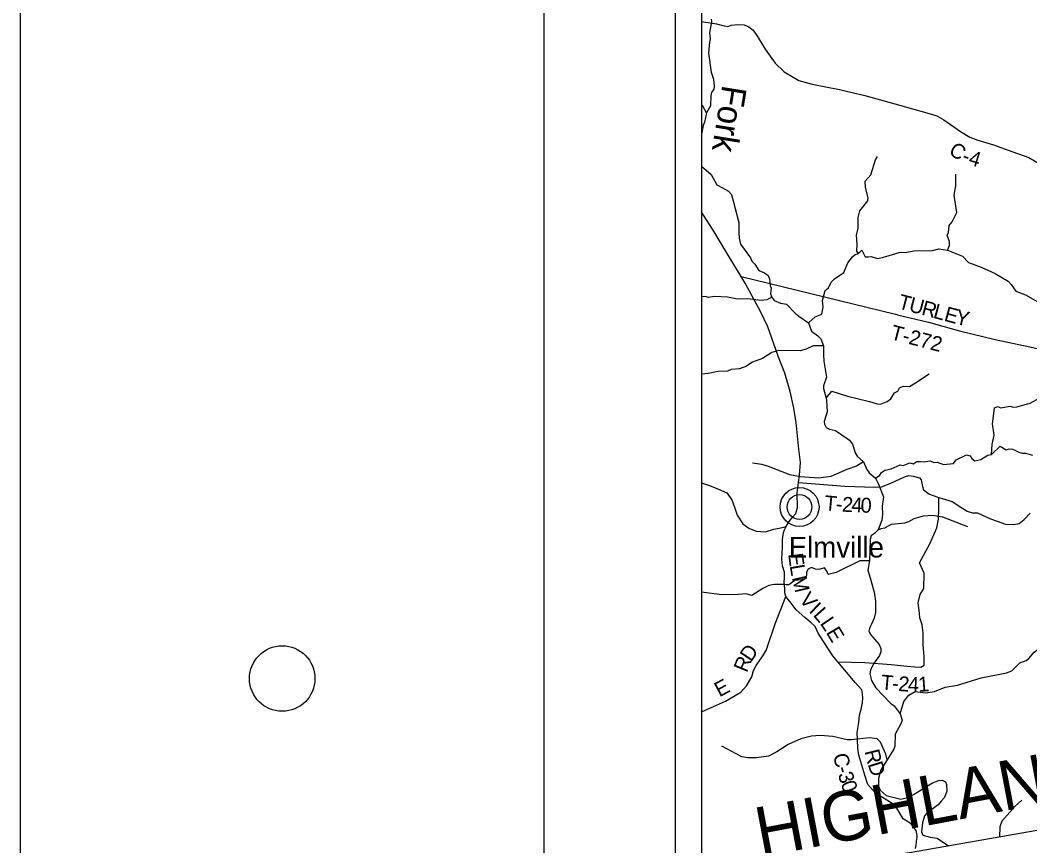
# Model space of a CAD drawing. Extents: x 0 to 34, y 0 to 22.
# Drawn here: x 0 to 3.854, y 14.612 to 17.761 of the extents above; entities that cross this region are included whole.
import ezdxf

# ---------------------------------------------------------------- set-up
doc = ezdxf.new("R2010")
doc.units = 0
for name, color, linetype in [('GM_X_Adjacent_County', 7, 'Continuous'), ('GM_X_Adjacent_County_Text', 7, 'Continuous'), ('GM_X_County', 7, 'Continuous'), ('GM_X_County_Road', 7, 'Continuous'), ('GM_X_County_Road_Text', 7, 'Continuous'), ('GM_X_Minor_River', 7, 'Continuous'), ('GM_X_Minor_River_Text', 7, 'Continuous'), ('GM_X_Township_Road', 7, 'Continuous'), ('GM_X_Township_Road_Text', 7, 'Continuous'), ('GM_X_Township_ROW', 7, 'Continuous'), ('GM_X_Unincorporated', 7, 'Continuous'), ('GM_X_Unincorporated_Location', 7, 'Continuous'), ('GM_X_Unincorporated_Text', 7, 'Continuous'), ('SH_Border', 7, 'Continuous'), ('SH_Cut_Line', 7, 'Continuous'), ('SH_Data', 7, 'Continuous')]:
    doc.layers.add(name, color=color, linetype=linetype)

msp = doc.modelspace()

# ---------------------------------------------------------------- linework, layer by layer
at = {"layer": 'GM_X_Adjacent_County'}
msp.add_lwpolyline([(9.4, 14.9965), (8.815, 15.0315), (8.2967, 15.0626), (8.1206, 15.0731), (7.1103, 15.1434), (6.9032, 15.1545), (6.5214, 15.204), (6.1992, 15.1249), (5.0219, 14.8699), (4.9843, 14.8636), (3.402, 14.5859), (3.2736, 14.5654), (2.6, 14.46)], dxfattribs=at)
at = {"layer": 'GM_X_County'}
msp.add_lwpolyline([(7.6111, 20.9006), (2.6, 20.9006), (2.6, 14.46)], dxfattribs=at)
at = {"layer": 'GM_X_County_Road'}
for points in [[(2.6, 17.757), (2.6572, 17.7478), (2.6864, 17.7403), (2.7016, 17.7378), (2.7156, 17.742), (2.7376, 17.7456), (2.7638, 17.7435), (2.7809, 17.736), (2.798, 17.724), (2.8149, 17.6998), (2.8432, 17.6514), (2.8819, 17.5973), (2.9155, 17.5645), (2.9722, 17.5311), (3.0227, 17.5173), (3.1271, 17.4975), (3.2243, 17.4742), (3.3387, 17.4422), (3.4154, 17.4207), (3.4519, 17.4103), (3.4994, 17.3969), (3.5256, 17.3819), (3.5896, 17.3364), (3.6247, 17.3153), (3.6547, 17.3034), (3.7155, 17.2859), (3.7888, 17.2594), (3.8496, 17.2378), (3.8934, 17.2122)], [(3.4175, 14.6019), (3.4198, 14.6133), (3.4216, 14.6286), (3.4225, 14.6372), (3.4231, 14.6451), (3.4232, 14.6521), (3.4229, 14.6572), (3.4215, 14.664), (3.4195, 14.6697), (3.415, 14.6769), (3.4011, 14.6957), (3.3707, 14.7144), (3.3562, 14.7394), (3.3435, 14.759), (3.3279, 14.7733), (3.2776, 14.8049), (3.2559, 14.8234), (3.2356, 14.8453), (3.224, 14.8809), (3.2015, 14.957), (3.1976, 14.9851), (3.1949, 15.0439), (3.2007, 15.0819), (3.2036, 15.11), (3.2095, 15.1328), (3.2147, 15.1567), (3.2168, 15.1757), (3.2156, 15.1917), (3.2128, 15.2068), (3.1872, 15.2351), (3.1205, 15.3137), (3.1013, 15.3363), (3.0656, 15.3908), (3.0461, 15.4225), (3.0345, 15.449), (3.0178, 15.4633), (2.9949, 15.4829), (2.9621, 15.5116), (2.9433, 15.538), (2.9219, 15.5633), (2.9192, 15.5766), (2.9183, 15.5898), (2.9159, 15.6213), (2.9173, 15.632), (2.9172, 15.6555), (2.9094, 15.6797), (2.9077, 15.7048), (2.9097, 15.7511), (2.9103, 15.7803), (2.9139, 15.8069), (2.9173, 15.8175), (2.9236, 15.8297), (2.9352, 15.8491), (2.9492, 15.8671), (2.9612, 15.88), (2.9668, 15.9028), (2.9656, 15.9567), (2.9713, 15.9982), (2.9751, 16.0258), (2.9782, 16.0744), (2.9714, 16.1252), (2.962, 16.2265), (2.9529, 16.2811), (2.9389, 16.3444), (2.9183, 16.4152), (2.8936, 16.48), (2.8535, 16.5921), (2.8262, 16.6507), (2.7674, 16.7585), (2.752, 16.784), (2.7027, 16.8655), (2.6456, 16.9601), (2.6077, 17.0172), (2.6, 17.0296)], [(2.6, 15.9971), (2.6306, 15.9865), (2.666, 15.9723), (2.6968, 15.9585), (2.7167, 15.932), (2.7279, 15.8999), (2.7371, 15.8737), (2.7586, 15.8401), (2.7807, 15.8235), (2.8092, 15.8116), (2.8445, 15.8095), (2.877, 15.8203), (2.8971, 15.8242), (2.9236, 15.8297)]]:
    msp.add_lwpolyline(points, dxfattribs=at)
at = {"layer": 'GM_X_Minor_River'}
for points in [[(2.6379, 17.7657), (2.6386, 17.7547), (2.6306, 17.7135), (2.6338, 17.6907), (2.631, 17.6778), (2.6268, 17.6351), (2.6378, 17.5626), (2.6458, 17.5367), (2.649, 17.5101), (2.647, 17.498), (2.6393, 17.4852), (2.6358, 17.4727), (2.6346, 17.4348), (2.62, 17.4077), (2.6124, 17.3721), (2.6063, 17.3601), (2.6, 17.3267)], [(2.62, 17.4077), (2.6062, 17.434), (2.6, 17.4372)], [(3.1996, 16.8718), (3.1932, 16.8802), (3.195, 16.9074), (3.1923, 16.9412), (3.1979, 16.968), (3.1987, 17.009), (3.2053, 17.0339), (3.2352, 17.0719), (3.2369, 17.0844), (3.227, 17.1228), (3.2254, 17.1474), (3.2464, 17.1715), (3.2644, 17.2282), (3.2717, 17.2414)], [(2.6, 17.204), (2.6373, 17.1729), (2.6596, 17.134), (2.6807, 17.1217), (2.7037, 17.1093), (2.7149, 17.0971), (2.7433, 16.9903), (2.7426, 16.9513), (2.7439, 16.9293), (2.7493, 16.9073), (2.7878, 16.8553), (2.7926, 16.8416), (2.8042, 16.8302), (2.8195, 16.8061), (2.8409, 16.798), (2.8545, 16.7872), (2.8596, 16.775), (2.862, 16.7492), (2.8668, 16.7393), (2.864, 16.7185), (2.8673, 16.7067), (2.8774, 16.6926), (2.9015, 16.6825), (2.9253, 16.6781), (2.9597, 16.6422), (2.9717, 16.6318), (3.0093, 16.6072), (3.0203, 16.5745), (3.0448, 16.5572), (3.0564, 16.5457), (3.0667, 16.5198), (3.0667, 16.4857), (3.0676, 16.4611), (3.0776, 16.4), (3.0663, 16.3667), (3.0658, 16.3561), (3.0768, 16.32), (3.0771, 16.3102), (3.0805, 16.2673), (3.0684, 16.2299), (3.0694, 16.22), (3.0769, 16.2071), (3.0897, 16.2013), (3.1123, 16.1965), (3.1563, 16.1654), (3.166, 16.1588), (3.1765, 16.1443), (3.1868, 16.1105), (3.1942, 16.0983), (3.2186, 16.0761), (3.2319, 16.0479), (3.2409, 16.0353), (3.2649, 16.0142), (3.276, 15.9918), (3.2952, 15.9435), (3.2899, 15.9075), (3.2919, 15.8768), (3.2894, 15.8541), (3.2747, 15.8171), (3.2617, 15.8051), (3.2483, 15.7939)], [(3.5398, 16.8847), (3.5468, 16.9025), (3.547, 16.9169), (3.5381, 16.9397), (3.5435, 16.9518), (3.5453, 16.9779), (3.5568, 16.9922), (3.5753, 17.0273), (3.5703, 17.0607), (3.5654, 17.0941), (3.5714, 17.13), (3.5715, 17.1747)], [(3.0093, 16.6072), (3.0349, 16.6293), (3.06, 16.64), (3.0644, 16.6673), (3.0627, 16.6916), (3.0722, 16.7297), (3.0852, 16.7402), (3.0956, 16.7625), (3.1082, 16.7753), (3.1436, 16.7992), (3.1595, 16.8361), (3.1775, 16.8583), (3.1874, 16.867), (3.1996, 16.8718), (3.2129, 16.8838), (3.2252, 16.8582), (3.2377, 16.8589), (3.2475, 16.8595), (3.272, 16.8525), (3.2917, 16.8557), (3.3547, 16.8748), (3.3642, 16.8766), (3.3782, 16.8746), (3.4112, 16.8814), (3.4819, 16.8823), (3.5062, 16.8892), (3.5398, 16.8847), (3.5839, 16.8665), (3.5967, 16.8614), (3.6199, 16.8366), (3.6686, 16.8194), (3.7217, 16.7954), (3.7713, 16.7657), (3.7826, 16.7527), (3.8008, 16.7279), (3.837, 16.7139), (3.8841, 16.6869)], [(2.8673, 16.7067), (2.8631, 16.7011), (2.8498, 16.6944), (2.8285, 16.692), (2.7779, 16.6989), (2.7378, 16.6974), (2.6993, 16.7042), (2.6501, 16.7077), (2.6277, 16.703), (2.6164, 16.7077), (2.6, 16.7055)], [(3.0667, 16.5198), (3.0266, 16.5191), (3, 16.5069), (2.9768, 16.5006), (2.8963, 16.501), (2.8693, 16.4934), (2.8339, 16.4706), (2.7952, 16.4566), (2.77, 16.4398), (2.745, 16.4309), (2.7132, 16.4286), (2.7003, 16.4219), (2.6647, 16.4215), (2.6264, 16.4131), (2.6, 16.4117)], [(3.0768, 16.32), (3.0979, 16.346), (3.1583, 16.3268), (3.2421, 16.3074), (3.2711, 16.298), (3.2839, 16.2964), (3.309, 16.3064), (3.3227, 16.3176), (3.3373, 16.3398), (3.3499, 16.3465), (3.3564, 16.3586), (3.3697, 16.3653), (3.3943, 16.3639), (3.4179, 16.3781), (3.4697, 16.412)], [(3.7073, 16.1046), (3.7103, 16.1425), (3.7179, 16.178), (3.7111, 16.2213), (3.7173, 16.2709), (3.7193, 16.283), (3.7307, 16.2874), (3.7427, 16.2828), (3.778, 16.2896), (3.7908, 16.2853), (3.8037, 16.286), (3.8549, 16.3002), (3.88, 16.314), (3.8917, 16.3128), (3.9168, 16.3243), (3.9429, 16.3244), (3.9649, 16.3329)], [(3.2649, 16.0142), (3.2813, 16.0255), (3.2882, 16.0356), (3.3004, 16.045), (3.3246, 16.0497), (3.3585, 16.0652), (3.3705, 16.0632), (3.3956, 16.0725), (3.4084, 16.0693), (3.4218, 16.0779), (3.4361, 16.0781), (3.4475, 16.0761), (3.4733, 16.0808), (3.4868, 16.0746), (3.4997, 16.0748), (3.5246, 16.0659), (3.5621, 16.0708), (3.5732, 16.0844), (3.6123, 16.1037), (3.6259, 16.0994), (3.6319, 16.0895), (3.6439, 16.081), (3.6666, 16.0857), (3.694, 16.1025), (3.7073, 16.1046), (3.7409, 16.1361), (3.7631, 16.1223), (3.7745, 16.126), (3.7877, 16.1254), (3.7994, 16.1196), (3.8118, 16.1131), (3.825, 16.1092), (3.8375, 16.1102), (3.8639, 16.1016)], [(3.2186, 16.0761), (3.1923, 16.0604), (3.1547, 16.0472), (3.0939, 16.0201), (3.0481, 16.0141), (2.977, 16.019), (2.9377, 16.0273), (2.8567, 16.0588), (2.8303, 16.0666), (2.7955, 16.0719)], [(3.2747, 15.8171), (3.2861, 15.8227), (3.3001, 15.8244), (3.326, 15.8389), (3.3767, 15.8445), (3.3919, 15.8493), (3.4121, 15.8608), (3.4481, 15.8707), (3.4818, 15.873), (3.5207, 15.8662), (3.6164, 15.8296)], [(3.2483, 15.7939), (3.244, 15.7803), (3.2417, 15.6992), (3.2357, 15.6632), (3.2437, 15.6347), (3.2595, 15.5793), (3.2652, 15.5455), (3.2644, 15.5015), (3.2596, 15.4807), (3.2496, 15.4569), (3.2434, 15.4445), (3.2398, 15.432), (3.2454, 15.4183), (3.2791, 15.3801), (3.285, 15.3649), (3.2848, 15.3524), (3.2794, 15.3384), (3.2571, 15.3057), (3.2459, 15.2823), (3.2435, 15.2683), (3.2489, 15.2425), (3.2665, 15.2146), (3.3223, 15.1561), (3.3365, 15.1461), (3.3589, 15.1148), (3.3659, 15.0908), (3.3616, 15.0776), (3.3396, 15.0377), (3.3388, 14.9918), (3.3341, 14.9801), (3.309, 14.9394)], [(3.2417, 15.6992), (3.2046, 15.6984), (3.1142, 15.655), (3.0846, 15.6469), (3.0783, 15.6591), (3.0704, 15.6721), (3.0488, 15.6655), (3.0352, 15.6667), (3.0201, 15.6729), (3.008, 15.6674), (3.001, 15.6553), (3.0009, 15.6424), (2.9947, 15.63), (2.9818, 15.626), (2.9568, 15.6239), (2.934, 15.6075), (2.9234, 15.6068), (2.9132, 15.6081), (2.8795, 15.6084), (2.8571, 15.6044), (2.834, 15.5937), (2.7925, 15.5664), (2.7698, 15.5727), (2.7414, 15.5703), (2.6775, 15.5695), (2.6, 15.5795)], [(3.3589, 15.1148), (3.3734, 15.162), (3.3918, 15.1869), (3.4161, 15.201), (3.4558, 15.1949), (3.4899, 15.1999), (3.5306, 15.2166), (3.5772, 15.2241), (3.6683, 15.2523), (3.7649, 15.2711), (3.7851, 15.2796), (3.8152, 15.3096), (3.8395, 15.3181), (3.8495, 15.326), (3.8698, 15.3508), (3.9109, 15.3808)], [(3.309, 14.9394), (3.3044, 14.9618), (3.2841, 15.0075), (3.2713, 15.0202), (3.2419, 15.0231), (3.1714, 15.0158), (3.1559, 15.0164), (3.1012, 15.0283), (3.0535, 15.0325), (3.0198, 15.0298), (2.98, 15.0196), (2.931, 14.9977), (2.8883, 14.9697), (2.8568, 14.9538), (2.8106, 14.9478), (2.7985, 14.9475), (2.7758, 14.9474), (2.7542, 14.9514), (2.6786, 14.9919)], [(3.309, 14.9394), (3.2853, 14.901), (3.2763, 14.8689), (3.276, 14.8393), (3.2823, 14.8237), (3.3048, 14.8038), (3.3618, 14.7903), (3.3872, 14.7962), (3.41, 14.8073), (3.4827, 14.8517), (3.5059, 14.8606), (3.5187, 14.8619), (3.5315, 14.8558), (3.5356, 14.8462), (3.5369, 14.8205), (3.5283, 14.7967), (3.5149, 14.7816), (3.5042, 14.7685), (3.46, 14.7367), (3.4523, 14.7258), (3.4445, 14.6997), (3.4407, 14.6649), (3.4459, 14.6519), (3.4727, 14.6448), (3.5003, 14.6404), (3.5432, 14.6119)], [(3.8233, 14.7855), (3.7976, 14.7631), (3.7471, 14.706), (3.7394, 14.6838), (3.7384, 14.6442)]]:
    msp.add_lwpolyline(points, dxfattribs=at)
at = {"layer": 'GM_X_Township_Road'}
for points in [[(3.3418, 16.6396), (3.3482, 16.638), (3.4669, 16.6089), (3.5849, 16.5759), (3.7215, 16.5433), (3.8532, 16.5156), (3.9924, 16.4841), (4.3578, 16.3948)], [(2.9713, 15.9982), (3.1482, 15.9844), (3.2226, 15.9814), (3.2636, 15.9798), (3.2874, 15.9807), (3.323, 15.995), (3.3589, 16.0119), (3.3793, 16.0207), (3.3918, 16.0246), (3.4089, 16.0224), (3.4321, 16.0161), (3.4386, 16.0074), (3.4444, 15.982), (3.4475, 15.9699), (3.4712, 15.9534), (3.5031, 15.9422), (3.5068, 15.941), (3.5574, 15.9251), (3.5905, 15.904), (3.6145, 15.8886), (3.6351, 15.8819), (3.6544, 15.8824), (3.673, 15.873), (3.7031, 15.8588), (3.7285, 15.8498), (3.7605, 15.8394), (3.7927, 15.8377), (3.8135, 15.8409), (3.832, 15.8569), (3.855, 15.881)], [(2.6, 15.1233), (2.6923, 15.1631), (2.7505, 15.1985), (2.7726, 15.2219), (2.7932, 15.257), (2.799, 15.2802), (2.8093, 15.3002), (2.8326, 15.3327), (2.8475, 15.3569), (2.8817, 15.4581), (2.9219, 15.5633)], [(3.1205, 15.3137), (3.2236, 15.3114), (3.3244, 15.3041), (3.3858, 15.2977), (3.4149, 15.2949), (3.4373, 15.2936), (3.4499, 15.3011), (3.45, 15.3338), (3.4464, 15.3782), (3.447, 15.4241), (3.4426, 15.4549), (3.434, 15.4819), (3.4322, 15.4991)]]:
    msp.add_lwpolyline(points, dxfattribs=at)
at = {"layer": 'GM_X_Township_ROW'}
for points in [[(2.752, 16.784), (3.3414, 16.6397), (3.3418, 16.6396)], [(3.4322, 15.4991), (3.4321, 15.4995), (3.4279, 15.5385), (3.4348, 15.5707), (3.4486, 15.5934), (3.4508, 15.6522), (3.4331, 15.6914), (3.4718, 15.7641), (3.499, 15.8243), (3.5056, 15.858), (3.5058, 15.8956), (3.5068, 15.941)]]:
    msp.add_lwpolyline(points, dxfattribs=at)
at = {"layer": 'GM_X_Unincorporated'}
for radius in [0.0744, 0.0472]:
    msp.add_circle((2.9747, 15.9043), radius, dxfattribs=at)
at = {"layer": 'GM_X_Unincorporated_Location'}
msp.add_line((2.9747, 15.9043), (2.9747, 15.9043), dxfattribs=at)
at = {"layer": 'SH_Border'}
msp.add_lwpolyline([(2, 21.5), (33.5, 21.5), (33.5, 0.5), (2, 0.5)], close=True, dxfattribs=at)
msp.add_circle((1, 15.25), 0.125, dxfattribs=at)
at = {"layer": 'SH_Cut_Line'}
msp.add_lwpolyline([(0, 0), (34, 0), (34, 22), (0, 22)], close=True, dxfattribs=at)
at = {"layer": 'SH_Data'}
for p, q in [((2.5, 21), (2.5, 14)), ((2.6, 20.9), (2.6, 14.1))]:
    msp.add_line(p, q, dxfattribs=at)

# ---------------------------------------------------------------- texts
at = {"layer": 'GM_X_Adjacent_County_Text'}
msp.add_text('HIGHLAND COUNTY', height=0.189394, rotation=10.7426, dxfattribs=at).set_placement((2.8262, 14.568))
at = {"layer": 'GM_X_County_Road_Text'}
for s, rotation, p in [('C', 327.8353, (3.5404, 17.2526)), ('-', 338.7751, (3.5905, 17.2224)), ('4', 342.8142, (3.6163, 17.2125)), ('E', 277.3616, (2.9312, 15.7251)), ('L', 279.6904, (2.937, 15.6805)), ('M', 283.1153, (2.9449, 15.6351)), ('V', 309.3875, (2.9711, 15.5501)), ('I', 316.3635, (3.0079, 15.506)), ('L', 311.5189, (3.0239, 15.4909)), ('L', 304.1406, (3.0509, 15.4606)), ('E', 300.722, (3.0743, 15.4261)), ('C', 281.0551, (3.103, 14.9595)), ('R', 284.0665, (3.2224, 14.9723)), ('D', 287.2764, (3.2346, 14.9237)), ('3', 287.0163, (3.1205, 14.885)), ('-', 287.2584, (3.1136, 14.9072)), ('0', 288.5402, (3.1313, 14.85))]:
    msp.add_text(s, height=0.0568, rotation=rotation, dxfattribs=at).set_placement(p)
at = {"layer": 'GM_X_Minor_River_Text'}
msp.add_text('Fork', height=0.0947, rotation=260.8961, dxfattribs=at).set_placement((2.6803, 17.5171))
at = {"layer": 'GM_X_Township_Road_Text'}
for s, height, rotation, p in [('T', 0.0568, 345.0012, (3.3476, 16.6625)), ('U', 0.0568, 344.9954, (3.3887, 16.6515)), ('R', 0.0568, 344.9987, (3.437, 16.6385)), ('L', 0.0568, 345.0012, (3.482, 16.6265)), ('E', 0.0568, 345.0844, (3.5232, 16.6154)), ('Y', 0.0568, 346.5726, (3.5658, 16.6041)), ('T-272', 0.05682, 345.4273, (3.3187, 16.5452)), ('T', 0.0568, 354.7943, (3.0681, 15.8926)), ('2', 0.0568, 356.7853, (3.1359, 15.8868)), ('4', 0.0568, 357.7466, (3.1718, 15.8848)), ('0', 0.0568, 358.0486, (3.2071, 15.8834)), ('-', 0.0568, 355.8222, (3.1116, 15.8886)), ('D', 0.0568, 55.6087, (2.7895, 15.3103)), ('R', 0.0568, 67.626, (2.7733, 15.2699)), ('T', 0.0568, 354.8847, (3.2836, 15.2084)), ('E', 0.0568, 28.0045, (2.669, 15.178)), ('-', 0.0568, 355.0613, (3.3261, 15.2046)), ('2', 0.0568, 355.7773, (3.3501, 15.2026)), ('4', 0.0568, 358.2005, (3.3876, 15.1998)), ('1', 0.0568, 3.9968, (3.4289, 15.1989))]:
    msp.add_text(s, height=height, rotation=rotation, dxfattribs=at).set_placement(p)
at = {"layer": 'GM_X_Unincorporated_Text'}
msp.add_text('Elmville', height=0.07898, rotation=0, dxfattribs=at).set_placement((2.9332, 15.7115))

doc.saveas('drawing.dxf')
